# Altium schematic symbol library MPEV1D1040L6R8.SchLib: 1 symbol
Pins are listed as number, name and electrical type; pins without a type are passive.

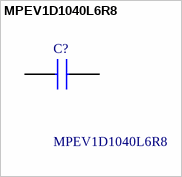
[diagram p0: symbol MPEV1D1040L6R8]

## MPEV1D1040L6R8
designator C?
KEMET, MPEV, Power, 6.8 uH, 20%, 180C, -55C, 4340, 8.3 A, 24.1 mOhms, 14 MHz, 500, 10.8mm, 11.1mm, 10mm, 10.2mm, 4mm, 4mm
footprint INDPM108100X400N
pins: 1, 2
